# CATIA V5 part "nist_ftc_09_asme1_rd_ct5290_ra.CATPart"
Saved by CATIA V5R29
Part number: NIST PMI FTC 09 ASME1
Revision: D
Description: NIST PMI test model downloaded from http://go.usa.gov/mGVm
Bounding box of the stored display mesh (mm): x -95.25 to 95.25, y 0 to 9.642, z -139.7 to 139.7
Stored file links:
  E:\users\dgn\TPS V5\Import-export annotations\Step\PMI representation 2015\NIST UC\FTC\R29\nist_ftc_09_asme1_ct5240_rd - V5R29 test.CATPart
  E:\users\dgn\TPS V5\Import-export annotations\Step\PMI representation 2015\NIST UC\nist_ftc_09_asme1_ct5240_rd - 0.CATPart
  E:\DownloadOfCXR29\win_b64\resources\graphic\CATTPSGeneralTolerance.xlsx
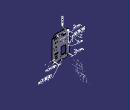
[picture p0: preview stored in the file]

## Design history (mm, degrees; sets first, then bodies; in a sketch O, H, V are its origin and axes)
TTRSSet1
f4a2d38f3ddc11d3a929006094b99c4b_11 "CATTPSSet"
Set1 "MBD_A_PMI"
  Plane1: type Equation, A -0.57735, B 0.57735, C 0.57735, Length 20, RefPoint vertex [face of Chamfer4 | end face of Pad1 | face of Pad1 from Sketch7.L15]
  Point1: type Center, Curve edge [end face of Pad1 | face of Chamfer1]
  Plane2: type OffsetPt, RefPlane face of Pad1 from Sketch7.L15, RefPoint Point1
  Intersect1: ToIntersect1 Chamfer1, ToIntersect2 Plane2
Set2 "MBD_B"
  Sketch1 on end face of Pad1, origin (0, 3.0378, 0), H (-1, 0, 0), V (0, 0, 1)
    arc A1 centre (-50.8, 12.7) radius 34.29 from (-66.509, -17.78) to (-81.28, -3.009) ccw
    point P1 (-50.8, 12.7)
    point P2 (-81.28, -3.009)
    point P3 (-66.509, -17.78)
    line L1 (-64.0699, -20.2137) -> (-63.1677, -17.9758)
    point P5 (-63.1677, -17.9758)
    line L2 (-81.28, -3.009) -> (-83.717, -0.5681)
    line L3 (-83.717, -0.5681) -> (-81.4789, 0.334)
    line L4 (-81.4789, 0.334) -> (-81.28, -3.009)
    polyline C1
    construction line L5 (-50.8, 12.7) -> (-53.3201, 12.7)
    construction line L6 (-50.8, 12.7) -> (-50.8, 10.3697)
    reference projected arc E1 centre (-50.8, 12.7) radius 4.7625 from (-52.578, 17.1182) to (-49.022, 17.1182) ccw from edge [end face of Pad1 | face of Pocket2 from Sketch15.A1]
    point P10 (-63.6219, -19.1025)
    line L7 (-66.509, -17.78) -> (-63.1677, -17.9758)
    line L8 (-66.5086, -17.7802) -> (-64.0704, -20.2149)
    point P12 (-66.5086, -17.7802)
    point P13 (-64.0704, -20.2149)
    radius A1 = 34.29
    distance L5 P3 = 30.48
    distance L6 P2 = 30.48
    length L1 = 2.413
    distance L1 P3 = 3.1722
    angle L1 L7 = 71.3955
    length L8 = 3.4456
    angle L8 L1 = 67
    length L3 = 2.413
    distance L3 P2 = 3.175
    angle L3 L2 = 67
    coincidence: L1 P1, L3 P1, P10 L1, P10 A1, L7 P5, P12 A1, P13 L1
    horizontal: L5 H
    vertical: L6 V
    concentricity: E1 P1
  Sketch2 on end face of Pad1, origin (0, 3.0378, 0), H (-1, 0, 0), V (0, 0, 1)
    reference projected circle E1 centre (57.15, 38.4) radius 3.175 from edge [end face of Pad1 | face of RectPattern2]
    reference projected circle E2 centre (0.15, -101.6) radius 3.175 from edge [end face of Pad1 | face of RectPattern2]
    axis line L1 (0.15, -101.6) -> (57.15, 38.4)
    point P1 (0.15, -101.6)
    point P2 (57.15, 38.4)
    point P3 (28.65, -31.6)
    concentricity: P1 E2, P2 E1
    midpoint: P3 L1
    coincidence: P3 L1
  AxisSystem1 "AF": origin (-28.65, 3.0378, -31.6), X (1, 0, 0), Y (0, 1, 0), Z (0, 0, 1)
  AxisSystem2 "ABC": origin (-82.55, 3.0378, 107.95), X (1, 0, 0), Y (0, 0, -1), Z (0, 1, 0)
Set3 "MBD_C"
  Sketch3 on end face of Pad1, origin (0, 3.0378, 0), H (-1, 0, 0), V (0, 0, 1)
    reference projected circle E1 centre (-50.8, -15.24) radius 1.9844 from edge [end face of Pad1 | face of Hole7]
    point P1 (-50.8, -15.24)
    line L1 (-50.8, -10.16) -> (-50.8, -20.32)
    point P2 (-50.8, -10.16)
    reference projected circle E2 centre (-78.74, 12.7) radius 1.9844 from edge [end face of Pad1 | face of CircPattern1]
    point P4 (-78.74, 12.7)
    line L2 (-83.82, 12.7) -> (-73.66, 12.7)
    point P5 (-83.82, 12.7)
    reference projected circle E3 centre (-70.5566, -7.0566) radius 1.9844 from edge [end face of Pad1 | face of CircPattern1]
    line L3 (-66.9645, -3.4645) -> (-74.1487, -10.6487)
    point P7 (-66.9645, -3.4645)
    point P8 (-74.1487, -10.6487)
    point P9 (-70.5566, -7.0566)
    point P10 (-50.8, 12.7)
    point P11 (-66.6352, -10.3194)
    arc A1 centre (-50.8, 12.7) radius 27.94 from (-73.8194, -3.1352) to (-66.6352, -10.3194) ccw
    point P12 (-73.8194, -3.1352)
    construction line L4 (-50.8, 12.7) -> (-89.9713, -15.3816)
    angle L1 L3 = 45
    radius A1 = 27.94
    length L2 = 10.16
    distance P4 P5 = 5.08
    length L3 = 10.16
    distance P9 P8 = 5.08
    length L1 = 10.16
    distance P1 P2 = 5.08
    distance L3 P12 = 5.08
    distance L3 P11 = 5.08
    concentricity: P1 E1, P4 E2, P9 E3
    vertical: L1 V
    coincidence: L1 P1, L2 P4, P9 L3, P10 L3, P10 L2
    horizontal: L2 H
  AxisSystem3 "AGH": origin (50.8, 3.0378, 12.7), X (1, 0, 0), Y (0, 0, -1), Z (0, 1, 0)
  Sketch4 on end face of Pad1, origin (0, 3.0378, 0), H (-1, 0, 0), V (0, 0, 1)
    arc A1 centre (-50.8, 12.7) radius 25.9556 from (-69.1534, -5.6534) to (-72.7556, -1.1436) cw
    point P2 (-69.1534, -5.6534)
    reference projected circle E1 centre (-70.5566, -7.0566) radius 1.9844 from edge [end face of Pad1 | face of CircPattern1]
    reference projected arc E2 centre (-50.8, 12.7) radius 27.94 from (-73.8194, -3.1352) to (-66.6352, -10.3194) ccw from Sketch3.A1
    reference projected line E3 (-66.9645, -3.4645) -> (-74.1487, -10.6487) from Sketch3.L3
    arc A2 centre (-50.8, 12.7) radius 29.9244 from (-71.9597, -8.4597) to (-76.2178, -3.0926) cw
    point P5 (-71.9597, -8.4597)
    reference projected circle E4 centre (-70.5566, -7.0566) radius 1.9844 from edge [end face of Pad1 | face of CircPattern1]
    reference projected arc E5 centre (-50.8, 12.7) radius 27.94 from (-73.8194, -3.1352) to (-66.6352, -10.3194) ccw from Sketch3.A1
    reference projected line E6 (-66.9645, -3.4645) -> (-74.1487, -10.6487) from Sketch3.L3
    tangency: A1 E1, A2 E4
    concentricity: A1 E2, A2 E5
    coincidence: P2 E3, P5 E6
  Sketch5 on end face of Pad1, origin (0, 3.0378, 0), H (-1, 0, 0), V (0, 0, 1)
    line L1 (-50.8, 12.7) -> (-77.7835, -8.4552)
    point P1 (-50.8, 12.7)
    point P3 (-74.3496, -5.763)
    reference projected arc E1 centre (-50.8, 12.7) radius 29.9244 from (-76.2178, -3.0926) to (-71.9597, -8.4597) ccw from Sketch4.A2
    reference projected point E2 (-50.8, 12.7) from vertex [YZ plane of AxisSystem3 | ZX plane of AxisSystem3 | XY plane of AxisSystem3]
    point P4 (-71.2263, -3.3144)
    reference projected arc E3 centre (-50.8, 12.7) radius 25.9556 from (-72.7556, -1.1436) to (-69.1534, -5.6534) ccw from Sketch4.A1
    coincidence: P3 L1, P3 E1, P1 E2, P4 L1, P4 E3
  Line1: type PtPt, FirstPoint Sketch3.P8, SecondPoint Sketch3.P7
  Extrude1: Element1 Line1, Lim1 2.54, Lim2 0, Direction end face of Pad1
Set4 "MBD_D"
  Sketch6 on end face of Pad1, origin (0, 3.0378, 0), H (-1, 0, 0), V (0, 0, 1)
    reference projected circle E1 centre (-66.0374, 91.44) radius 3.5687 from edge [end face of Pad1 | face of RectPattern5]
    point P1 (-66.0374, 91.44)
    line L1 (-71.1174, 91.44) -> (-60.9574, 91.44)
    point P2 (-71.1174, 91.44)
    line L2 (-66.0374, 96.52) -> (-66.0374, 86.36)
    point P4 (-66.0374, 96.52)
    length L2 = 10.16
    distance P4 L1 = 5.08
    length L1 = 10.16
    distance P2 L2 = 5.08
    concentricity: P1 E1
    horizontal: L1 H
    coincidence: P1 L1, P1 L2
    vertical: L2 V
  AxisSystem4 "ADB": origin (-31.75, 3.0378, 91.44), X (1, 0, 0), Y (0, 0, -1), Z (0, 1, 0)
  AxisSystem5 "ABC": origin (-82.55, 3.0378, 107.95), X (1, 0, 0), Y (0, 0, -1), Z (0, 1, 0)
Set5 "MBD_A"
  AxisSystem6 "ABC": origin (-82.55, 3.0378, 107.95), X (1, 0, 0), Y (0, 0, -1), Z (0, 1, 0)
Set6
  Point2: type Center, Curve edge [end face of Pad1 | face of Chamfer1]
  Point3: type Center, Curve edge [end face of Pad1 | face of Pocket2 from Sketch15.A1]
  Point4: type Center, Curve edge [end face of Pad1 | face of Hole5]
  Plane3: type Between, Element1 face of Pocket3 from Sketch17.L3, Element2 face of Pocket3 from Sketch17.L2, Ratio 0.5
  Extract1: ExtractElem face of Pocket3 from Sketch17.A2
  Extract2: ExtractElem face of Pocket3 from Sketch17.A1
  Intersect2: ToIntersect1 Plane3, ToIntersect2 Extract1
  Intersect3: ToIntersect1 Plane3, ToIntersect2 Extract2
  Point5: type OnCurve, Support Intersect2, Ratio 0.5
  Point6: type OnCurve, Support Intersect3, Ratio 0.5
  Plane4: type Tangent, Support Extract1, RefPoint Point5
  Plane5: type Tangent, Support Extract2, RefPoint Point6
  Plane6: type Between, Element1 face of RectPattern6, Element2 face of RectPattern6, Ratio 0.5
  Extract3: ExtractElem face of RectPattern6
  Extract4: ExtractElem face of RectPattern6
  Intersect4: ToIntersect1 Plane6, ToIntersect2 Extract4
  Intersect5: ToIntersect1 Plane6, ToIntersect2 Extract3
  Point7: type OnCurve, Support Intersect4, Ratio 0.5
  Point8: type OnCurve, Support Intersect5, Ratio 0.5
  Plane7: type Tangent, Support Extract4, RefPoint Point7
  Plane8: type Tangent, Support Extract3, RefPoint Point8
Body1 (main body)
  Sketch7 on zx-plane, origin (0, 0, 0), H (-1, 0, 0), V (0, 0, 1)
    line L1 (-74.6125, 139.7) -> (74.6125, 139.7)
    line L2 (95.25, 117.475) -> (95.25, -117.475)
    construction line L3 (74.6125, -139.7) -> (-74.6125, -139.7)
    line L4 (-95.25, -117.475) -> (-95.25, 117.475)
    construction line L5 (0, -160) -> (0, 150)
    axis line L6 (150, 0) -> (-110, 0)
    line L7 (-74.6125, 139.7) -> (-74.6125, 117.475)
    line L8 (-74.6125, 117.475) -> (-95.25, 117.475)
    line L9 (74.6125, 139.7) -> (74.6125, 117.475)
    line L10 (74.6125, 117.475) -> (95.25, 117.475)
    line L11 (-95.25, -117.475) -> (-74.6125, -117.475)
    line L12 (-74.6125, -117.475) -> (-74.6125, -139.7)
    line L13 (95.25, -117.475) -> (74.6125, -117.475)
    line L14 (74.6125, -117.475) -> (74.6125, -139.7)
    line L15 (-74.6125, -139.7) -> (74.6125, -139.7)
    distance L1 L3 = 279.4
    distance L4 L2 = 190.5
    distance L5 L4 = 95.25
    distance L3 L6 = 139.7
    length L4 = 234.95
    length L3 = 149.225
    distance L12 L5 = 74.6125
    distance L6 L11 = 117.475
    horizontal: L6 H, L3 H, L1 H, L8 H, L10 H, L11 H, L13 H
    coincidence: L5 V, L6 H, L10 L8, L14 L9, L11 L13, L12 L7
    vertical: L2 V, L4 V, L14 V, L9 V, L12 V, L7 V
  Pad1: profile Sketch7, direction (0, 1, 0), length 3.0378
  Sketch8 on end face of Pad1, origin (75.874, 3.0378, 103.1133), H (1, 0, 0), V (0, 0, -1)
    point P1 (6.676, -4.8367)
    reference intersected line E1 through (-75.874, 0) direction (0, 1) from yz-plane
    reference intersected line E2 through (0, 103.1133) direction (1, 0) from xy-plane
    distance P1 E1 = 82.55
    distance E2 P1 = 107.95
  Hole1: placed by Sketch8, at (82.55, 3.0378, 107.95) direction (0, -1, 0), diameter 5.9436, through (limit type 6)
  Fillet1: radius 6.35, on edge [face of Pad1 from Sketch7.L8 | face of Pad1 from Sketch7.L7]; edge [face of Pad1 from Sketch7.L9 | face of Pad1 from Sketch7.L10]; edge [face of Pad1 from Sketch7.L13 | face of Pad1 from Sketch7.L14]; edge [face of Pad1 from Sketch7.L12 | face of Pad1 from Sketch7.L11]
  Sketch9 on end face of Pad1, origin (32.8752, 3.0378, 131.8981), H (1, 0, 0), V (0, 0, -1)
    point P1 (-13.8252, 261.4381)
    reference intersected line E2 through (-32.8752, 0) direction (0, 1) from yz-plane
    reference intersected line E3 through (0, 131.8981) direction (1, 0) from xy-plane
    distance P1 E2 = 19.05
    distance E3 P1 = 129.54
  Hole2: placed by Sketch9, at (19.05, 3.0378, -129.54) direction (0, -1, 0), diameter 6.35, through (limit type 6)
  RectPattern1: of Hole2, direction 1 instances 3, spacing 19.05, along edge [face of Pad1 from Sketch7.L1 | end face of Pad1] reversed
  Sketch10 on end face of Pad1, origin (53.7045, 3.0378, 105.0288), H (1, 0, 0), V (0, 0, -1)
    point P1 (-110.8545, 206.6288)
    reference intersected line E1 through (-53.7045, 0) direction (0, 1) from yz-plane
    reference intersected line E2 through (0, 105.0288) direction (1, 0) from xy-plane
    distance P1 E1 = 57.15
    distance E2 P1 = 101.6
  Hole3: placed by Sketch10, at (-57.15, 3.0378, -101.6) direction (0, -1, 0), diameter 6.35, through (limit type 6)
  RectPattern2: of Hole3, direction 1 instances 2, spacing 57, along edge [face of Pad1 from Sketch7.L1 | end face of Pad1], direction 2 instances 2, spacing 140, along edge [face of Pad1 from Sketch7.L4 | end face of Pad1] reversed
  Sketch11 on end face of Pad1, origin (0, 3.0378, 0), H (-1, 0, 0), V (0, 0, 1)
    point P1 (5.649, -11.6078)
    line L1 (5.649, -11.6078) -> (24.3053, -11.6078)
    line L2 (55.649, -11.6078) -> (55.649, -45.2528)
    line L3 (55.649, -91.6078) -> (37.0053, -91.6078)
    line L4 (5.649, -91.6078) -> (5.649, -57.9528)
    point P2 (55.649, -11.6078)
    point P4 (5.649, -91.6078)
    arc A1 centre (55.649, -51.6028) radius 6.35 from (55.649, -57.9528) to (55.649, -45.2528) ccw
    point P5 (55.649, -51.6028)
    arc A2 centre (30.6553, -11.6078) radius 6.35 from (37.0053, -11.6078) to (24.3053, -11.6078) ccw
    point P6 (30.6553, -11.6078)
    arc A3 centre (5.649, -51.6028) radius 6.35 from (5.649, -45.2528) to (5.649, -57.9528) ccw
    point P7 (5.649, -51.6028)
    arc A4 centre (30.6553, -91.6078) radius 6.35 from (24.3053, -91.6078) to (37.0053, -91.6078) ccw
    point P8 (30.6553, -91.6078)
    construction line L5 (30.6553, 11.6851) -> (30.6553, -11.6078)
    axis line L6 (55.649, -51.6028) -> (5.649, -51.6028)
    line L7 (55.649, -57.9528) -> (55.649, -91.6078)
    line L8 (5.649, -45.2528) -> (5.649, -11.6078)
    line L9 (37.0053, -11.6078) -> (55.649, -11.6078)
    line L10 (24.3053, -91.6078) -> (5.649, -91.6078)
    reference intersected line E1 through (0, 0) direction (-1, 0) from xy-plane
    reference intersected line E2 through (0, 0) direction (0, -1) from yz-plane
    distance L6 L3 = 40.005
    distance L5 L4 = 25.0063
    radius A2 = 6.35
    radius A1 = 6.35
    radius A4 = 6.35
    radius A3 = 6.35
    distance P4 P1 = 80
    distance P1 P2 = 50
    distance L9 E1 = 11.6078
    distance L8 E2 = 5.649
    horizontal: L1 H, L3 H
    vertical: L2 V, L4 V
    coincidence: P7 L4, P6 L1, P8 L3, P5 L2, P8 L5, L2 L7, L9 L1, L3 L10, L8 L4
  Pocket1: profile Sketch11, direction (0, -1, 0), through (limit type 6)
  RectPattern3: of Hole1, direction 1 instances 2, spacing 165.1, along edge [face of Pad1 from Sketch7.L1 | end face of Pad1] reversed, direction 2 instances 2, spacing 215.9, along edge [face of Pad1 from Sketch7.L4 | end face of Pad1]
  Chamfer1: length 0.762, second length 0.762, on edge [end face of Pad1 | face of Hole1]; edge [end face of Pad1 | face of RectPattern3] (x3)
  Chamfer2: length 6.35, second length 6.35, on edge [face of Pad1 from Sketch7.L4 | face of Pad1 from Sketch7.L8]; edge [face of Pad1 from Sketch7.L10 | face of Pad1 from Sketch7.L2]; edge [face of Pad1 from Sketch7.L11 | face of Pad1 from Sketch7.L4]; edge [face of Pad1 from Sketch7.L2 | face of Pad1 from Sketch7.L13]
  Chamfer3: length 12.7, angle 30, on edge [face of Pad1 from Sketch7.L7 | face of Pad1 from Sketch7.L1]; edge [face of Pad1 from Sketch7.L1 | face of Pad1 from Sketch7.L9]
  Chamfer4: length 12.7, angle 30, on edge [face of Pad1 from Sketch7.L15 | face of Pad1 from Sketch7.L12]; edge [face of Pad1 from Sketch7.L14 | face of Pad1 from Sketch7.L15]
  Sketch12 on end face of Pad1, origin (53.7613, 3.0378, -81.0134), H (1, 0, 0), V (0, 0, -1)
    point P1 (-104.5613, -172.4534)
    reference intersected line E1 through (0, -81.0134) direction (1, 0) from xy-plane
    reference intersected line E2 through (-53.7613, 0) direction (0, 1) from yz-plane
    distance P1 E1 = 91.44
    distance E2 P1 = 50.8
  Hole4: placed by Sketch12, at (-50.8, 3.0378, 91.44) direction (0, -1, 0), diameter 5.6134, through (limit type 6)
  RectPattern4: of Hole4, direction 1 instances 2, spacing 38.1, along edge [face of Pad1 from Sketch7.L15 | end face of Pad1] reversed, direction 2 instances 2, spacing 215.9
  Sketch13 on end face of Pad1, origin (33.0099, 3.0378, -92.3254), H (1, 0, 0), V (0, 0, -1)
    point P1 (-64.7599, -183.7654)
    reference intersected line E1 through (0, -92.3254) direction (1, 0) from xy-plane
    reference intersected line E2 through (-33.0099, 0) direction (0, 1) from yz-plane
    distance P1 E1 = 91.44
    distance E2 P1 = 31.75
  Hole5: placed by Sketch13, at (-31.75, 3.0378, 91.44) direction (0, -1, 0), diameter 19.05, through (limit type 6)
  Sketch14 on end face of Pad1, origin (-47.4372, 3.0378, -73.8358), H (1, 0, 0), V (0, 0, -1)
    point P1 (75.3745, -165.2758)
    reference intersected line E1 through (0, -73.8358) direction (1, 0) from xy-plane
    reference intersected line E2 through (47.4372, 0) direction (0, 1) from yz-plane
    distance E1 P1 = 91.44
    distance E2 P1 = 27.9374
  Hole6: placed by Sketch14, at (27.9374, 3.0378, 91.44) direction (0, -1, 0), diameter 7.1374, through (limit type 6)
  RectPattern5: of Hole6, direction 1 instances 3, spacing 19.05, along edge [face of Pad1 from Sketch7.L15 | end face of Pad1] reversed, direction 2 instances 2, spacing 215.9
  Sketch15 on end face of Pad1, origin (0, 3.0378, 0), H (-1, 0, 0), V (0, 0, 1)
    arc A1 centre (-50.8, 12.7) radius 4.7625 from (-52.578, 17.1182) to (-49.022, 17.1182) ccw
    point P1 (-50.8, 12.7)
    axis line L1 (-50.8, 12.7) -> (-50.8, 29.6508)
    line L2 (-52.578, 20.32) -> (-52.578, 17.1182)
    line L3 (-49.022, 20.32) -> (-49.022, 17.1182)
    arc A2 centre (-50.8, 20.32) radius 1.778 from (-49.022, 20.32) to (-52.578, 20.32) ccw
    point P3 (-50.8, 20.32)
    point P4 (-49.022, 20.32)
    reference intersected line E1 through (0, 0) direction (-1, 0) from xy-plane
    reference intersected line E2 through (0, 0) direction (0, -1) from yz-plane
    radius A1 = 4.7625
    distance L3 L2 = 3.556
    distance P1 P3 = 7.62
    distance E1 P1 = 12.7
    distance E2 L1 = 50.8
    vertical: L1 V, L2 V, L3 V
    coincidence: P3 L1, A2 P4, P4 L3
    tangency: A2 L3, A2 L2
  Pocket2: profile Sketch15, direction (0, -1, 0), through (limit type 6)
  Sketch16 on end face of Pad1, origin (-52.5866, 3.0378, 15.7994), H (1, 0, 0), V (0, 0, -1)
    point P1 (103.3866, 31.0394)
    reference intersected line E1 through (0, 15.7994) direction (1, 0) from xy-plane
    reference intersected line E2 through (52.5866, 0) direction (0, 1) from yz-plane
    distance P1 E1 = 15.24
    distance E2 P1 = 50.8
  Hole7: placed by Sketch16, at (50.8, 3.0378, -15.24) direction (0, -1, 0), diameter 3.9688, through (limit type 6)
  CircPattern1: of Hole7, instances 3, angular step 45, axis from face of Pocket2 from Sketch15.A1
  Sketch17 on end face of Pad1, origin (0, 3.0378, 0), H (-1, 0, 0), V (0, 0, 1)
    construction line L1 (-57.15, -95.25) -> (-38.1, -95.25)
    line L2 (-57.15, -92.075) -> (-38.1, -92.075)
    line L3 (-38.1, -98.425) -> (-57.15, -98.425)
    arc A1 centre (-38.1, -95.25) radius 3.175 from (-38.1, -92.075) to (-38.1, -98.425) cw
    arc A2 centre (-57.15, -95.25) radius 3.175 from (-57.15, -98.425) to (-57.15, -92.075) cw
    axis line L4 (-47.625, -92.075) -> (-47.625, -98.425)
    point P7 (-47.625, -92.075)
    point P8 (-47.625, -98.425)
    reference intersected line E1 through (0, 0) direction (-1, 0) from xy-plane
    reference intersected line E2 through (0, 0) direction (0, -1) from yz-plane
    distance L1 L2 = 3.175
    distance A2 A1 = 25.4
    distance E1 L1 = 95.25
    distance L4 E2 = 47.625
    horizontal: L1 H
    tangency: A1 L2, A2 L2, A1 L3, A2 L3
    vertical: L4 V
    midpoint: P7 L2, L3 P8
  Pocket3: profile Sketch17, direction (0, -1, 0), through (limit type 6)
  RectPattern6: of Pocket3, direction 1 instances 2, spacing 19.05, along edge [face of Pad1 from Sketch7.L2 | end face of Pad1], direction 2 instances 2, spacing 215.9
  Sketch18 on end face of Pad1, origin (0, 3.0378, 0), H (-1, 0, 0), V (0, 0, 1)
    construction line L1 (-61.9125, -50.8) -> (-33.3375, -50.8)
    line L2 (-61.9125, -46.0375) -> (-33.3375, -46.0375)
    line L3 (-33.3375, -55.5625) -> (-61.9125, -55.5625)
    arc A1 centre (-33.3375, -50.8) radius 4.7625 from (-33.3375, -46.0375) to (-33.3375, -55.5625) cw
    arc A2 centre (-61.9125, -50.8) radius 4.7625 from (-61.9125, -55.5625) to (-61.9125, -46.0375) cw
    axis line L4 (-47.625, -46.0375) -> (-47.625, -55.5625)
    point P7 (-47.625, -46.0375)
    point P8 (-47.625, -55.5625)
    reference intersected line E1 through (0, 0) direction (-1, 0) from xy-plane
    reference intersected line E2 through (0, 0) direction (0, -1) from yz-plane
    distance L1 L2 = 4.7625
    distance A2 A1 = 38.1
    distance L1 E1 = 50.8
    distance L4 E2 = 47.625
    horizontal: L1 H
    tangency: A1 L2, A2 L2, A1 L3, A2 L3
    coincidence: P7 L2, P8 L3
    vertical: L4 V
    midpoint: P8 L3, P7 L2
  Pocket4: profile Sketch18, direction (0, -1, 0), through (limit type 6)
  Sketch19 on end face of Pad1, origin (83.475, 3.0378, 19.7164), H (1, 0, 0), V (0, 0, -1)
    point P1 (-168.565, 38.7664)
    reference intersected line E1 through (0, 19.7164) direction (1, 0) from xy-plane
    reference intersected line E2 through (-83.475, 0) direction (0, 1) from yz-plane
    distance E1 P1 = 19.05
    distance E2 P1 = 85.09
  Hole8: placed by Sketch19, at (-85.09, 3.0378, -19.05) direction (0, -1, 0), diameter 6.35, through (limit type 6)
  RectPattern7: of Hole8, direction 1 instances 3, spacing 19.05, along edge [face of Pad1 from Sketch7.L4 | end face of Pad1] reversed, direction 2 instances 2, spacing 215.9
  Sketch20 on end face of Pad1, origin (46.5928, 3.0378, -111.2191), H (1, 0, 0), V (0, 0, -1)
    point P1 (-102.4728, -221.7091)
    reference intersected line E1 through (-46.5928, 0) direction (0, 1) from yz-plane
    reference intersected line E2 through (0, -111.2191) direction (1, 0) from xy-plane
    distance P1 E1 = 55.88
    distance P1 E2 = 110.49
  Hole9: placed by Sketch20, at (-55.88, 3.0378, 110.49) direction (0, -1, 0), diameter 3.9688, through (limit type 6)
  RectPattern8: of Hole9, direction 1 instances 2, spacing 10.16, along edge [face of Pad1 from Sketch7.L15 | end face of Pad1] reversed, direction 2 instances 2, spacing 215.9
  RectPattern9: of RectPattern8, direction 1 instances 2, spacing 38.1, along edge [face of Pad1 from Sketch7.L15 | end face of Pad1] reversed, direction 2 instances 2, spacing 215.9
  Sketch21 on end face of Pad1, origin (-44.0436, 3.0378, -67.034), H (1, 0, 0), V (0, 0, -1)
    point P1 (82.1436, -124.184)
    reference intersected line E1 through (44.0436, 0) direction (0, 1) from yz-plane
    reference intersected line E2 through (0, -67.034) direction (1, 0) from xy-plane
    distance E1 P1 = 38.1
    distance E2 P1 = 57.15
  Hole10: placed by Sketch21, at (38.1, 3.0378, 57.15) direction (0, -1, 0), diameter 8.001, through (limit type 6)
  RectPattern10: of Hole10, direction 1 instances 2, spacing 19.05, along edge [face of Pad1 from Sketch7.L15 | end face of Pad1] reversed, direction 2 instances 2, spacing 215.9
  Fillet2: radius 3.175, on edge [face of Pocket1 from Sketch11.L10 | face of Pocket1 from Sketch11.L4]; edge [face of Pocket1 from Sketch11.L8 | face of Pocket1 from Sketch11.L1]; edge [face of Pocket1 from Sketch11.L9 | face of Pocket1 from Sketch11.L2]; edge [face of Pocket1 from Sketch11.L7 | face of Pocket1 from Sketch11.L3]
  Sketch22 on end face of Pad1, origin (0, 3.0378, 0), H (-1, 0, 0), V (0, 0, 1)
    point P1 (-12.7, 118.11)
    reference intersected line E1 through (0, 0) direction (0, -1) from yz-plane
    reference intersected line E2 (-74.6125, 139.7) -> (74.6125, 139.7) from face of Pad1 from Sketch7.L1
    point P2 (-12.7, 118.11)
    point P3 (-12.7, 118.11)
    point P4 (-26.2068, 116.7906)
    point P5 (-32.4699, 114.5929)
    point P6 (-37.6134, 113.9143)
    point P7 (-38.7059, 115.0068)
    point P8 (-15.8025, 118.11)
    point P9 (-15.8025, 106.8665)
    point P10 (-15.8025, 118.11)
    point P11 (-16.7397, 106.501)
    point P12 (-15.8025, 106.8665)
    point P13 (-26.2068, 116.7906)
    point P14 (-16.7397, 106.501)
    point P15 (-32.4699, 103.11)
    point P16 (-32.4699, 114.5929)
    point P17 (-29.3377, 103.11)
    point P18 (-32.4699, 103.11)
    point P19 (-29.3377, 114.5181)
    point P20 (-29.3377, 103.11)
    point P21 (-28.62, 114.8343)
    point P22 (-29.3377, 114.5181)
    point P23 (-18.3552, 103.7339)
    point P24 (-28.62, 114.8343)
    point P25 (-18.3552, 103.7339)
    point P26 (-12.7, 105.9479)
    point P27 (-12.7, 105.9479)
    point P28 (-37.6134, 103.11)
    point P29 (-34.4811, 103.11)
    point P30 (-37.6134, 113.9143)
    point P31 (-37.6134, 103.11)
    point P32 (-53.4174, 115.0068)
    point P33 (-38.7059, 115.0068)
    point P34 (-53.4174, 115.0068)
    point P35 (-53.3599, 112.1904)
    point P36 (-44.3081, 112.1904)
    point P37 (-53.3599, 112.1904)
    point P38 (-43.9641, 103.11)
    point P39 (-44.3081, 112.1904)
    point P40 (-69.5674, 103.11)
    point P41 (-43.9641, 103.11)
    point P42 (-69.5674, 106.271)
    point P43 (-69.5674, 103.11)
    point P44 (-63.1581, 106.271)
    point P45 (-69.5674, 106.271)
    point P46 (-63.1581, 118.11)
    point P47 (-63.1581, 106.271)
    point P48 (-60.0556, 118.11)
    point P49 (-63.1581, 118.11)
    point P50 (-60.0556, 106.271)
    point P51 (-60.0556, 118.11)
    point P52 (-44.3655, 106.271)
    point P53 (-60.0556, 106.271)
    point P54 (-44.3655, 106.271)
    point P55 (-44.2506, 109.0871)
    point P56 (-53.8773, 109.0871)
    point P57 (-44.2506, 109.0871)
    point P58 (-53.8773, 118.11)
    point P59 (-53.8773, 109.0871)
    point P60 (-38.6768, 118.11)
    point P61 (-53.8773, 118.11)
    point P62 (-34.4811, 113.9143)
    point P63 (-38.6768, 118.11)
    point P64 (-34.4811, 103.11)
    point P65 (-34.4811, 113.9143)
    point P66 (-12.7, 118.11)
    point P67 (-12.7, 118.11)
    line L1 (-34.4811, 103.11) -> (-34.4811, 113.9143)
    arc A1 centre (-38.6768, 113.9143) radius 4.1957 from (-34.4811, 113.9143) to (-38.6768, 118.11) ccw
    line L2 (-38.6768, 118.11) -> (-53.8773, 118.11)
    arc A2 centre (-53.1589, 113.5985) radius 4.5683 from (-53.8773, 118.11) to (-53.8773, 109.0871) ccw
    line L3 (-53.8773, 109.0871) -> (-44.2506, 109.0871)
    arc A3 centre (-44.2506, 107.6767) radius 1.4104 from (-44.3655, 106.271) to (-44.2506, 109.0871) ccw
    line L4 (-44.3655, 106.271) -> (-60.0556, 106.271)
    line L5 (-60.0556, 106.271) -> (-60.0556, 118.11)
    line L6 (-60.0556, 118.11) -> (-63.1581, 118.11)
    line L7 (-63.1581, 118.11) -> (-63.1581, 106.271)
    line L8 (-63.1581, 106.271) -> (-69.5674, 106.271)
    line L9 (-69.5674, 106.271) -> (-69.5674, 103.11)
    line L10 (-69.5674, 103.11) -> (-43.9641, 103.11)
    arc A4 centre (-43.9641, 107.6567) radius 4.5467 from (-43.9641, 103.11) to (-44.3081, 112.1904) ccw
    line L11 (-44.3081, 112.1904) -> (-53.3599, 112.1904)
    arc A5 centre (-53.2372, 113.6017) radius 1.4166 from (-53.4174, 115.0068) to (-53.3599, 112.1904) ccw
    line L12 (-53.4174, 115.0068) -> (-38.7059, 115.0068)
    line L13 (-37.6134, 113.9143) -> (-37.6134, 103.11)
    line L14 (-37.6134, 103.11) -> (-34.4811, 103.11)
    line L15 (-12.7, 118.11) -> (-12.7, 105.9479)
    arc A6 centre (-15.961, 105.9479) radius 3.261 from (-18.3552, 103.7339) to (-12.7, 105.9479) ccw
    line L16 (-18.3552, 103.7339) -> (-28.62, 114.8343)
    arc A7 centre (-28.9245, 114.5528) radius 0.4146 from (-28.62, 114.8343) to (-29.3377, 114.5181) ccw
    line L17 (-29.3377, 114.5181) -> (-29.3377, 103.11)
    line L18 (-29.3377, 103.11) -> (-32.4699, 103.11)
    line L19 (-32.4699, 103.11) -> (-32.4699, 114.5929)
    line L20 (-26.2068, 116.7906) -> (-16.7397, 106.501)
    arc A8 centre (-16.3424, 106.8665) radius 0.5399 from (-16.7397, 106.501) to (-15.8025, 106.8665) ccw
    line L21 (-15.8025, 106.8665) -> (-15.8025, 118.11)
    line L22 (-15.8025, 118.11) -> (-12.7, 118.11)
    arc A9 centre (-38.7059, 113.9143) radius 1.0926 from (-37.6134, 113.9143) to (-38.7059, 115.0068) ccw
    arc A10 centre (-28.9528, 114.5929) radius 3.5171 from (-26.2068, 116.7906) to (-32.4699, 114.5929) ccw
    distance P1 E1 = 12.7
    distance E2 P1 = 21.59
    fix: P4, P5, P6, P7, P8, P9, P10, P11, P12, P13, P14, P15, P16, P17, P18, P19, P20, P21, P22, P23, P24, P25, P26, P27, P28, P29, P30, P31, P32, P33, P34, P35, P36, P37, P38, P39, P40, P41, P42, P43, P44, P45, P46, P47, P48, P49, P50, P51, P52, P53, P54, P55, P56, P57, P58, P59, P60, P61, P62, P63, P64, P65, L1, A1, L2, A2, L3, A3, L4, L5, L6, L7, L8, L9, L10, A4, L11, A5, L12, L13, L14, A6, L16, A7, L17, L18, L19, L20, A8, L21, A9, A10, L22, L15, P2
    coincidence: P66 P67
  Pocket5: profile Sketch22, direction (0, -1, 0), length 1.27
